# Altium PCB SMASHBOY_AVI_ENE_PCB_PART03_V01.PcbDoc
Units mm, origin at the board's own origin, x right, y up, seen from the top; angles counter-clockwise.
Board outline 215 x 83 mm, 2 copper layers (Top Layer, Bottom Layer); 21 components, 8 nets, 58 pads, 50 vias.
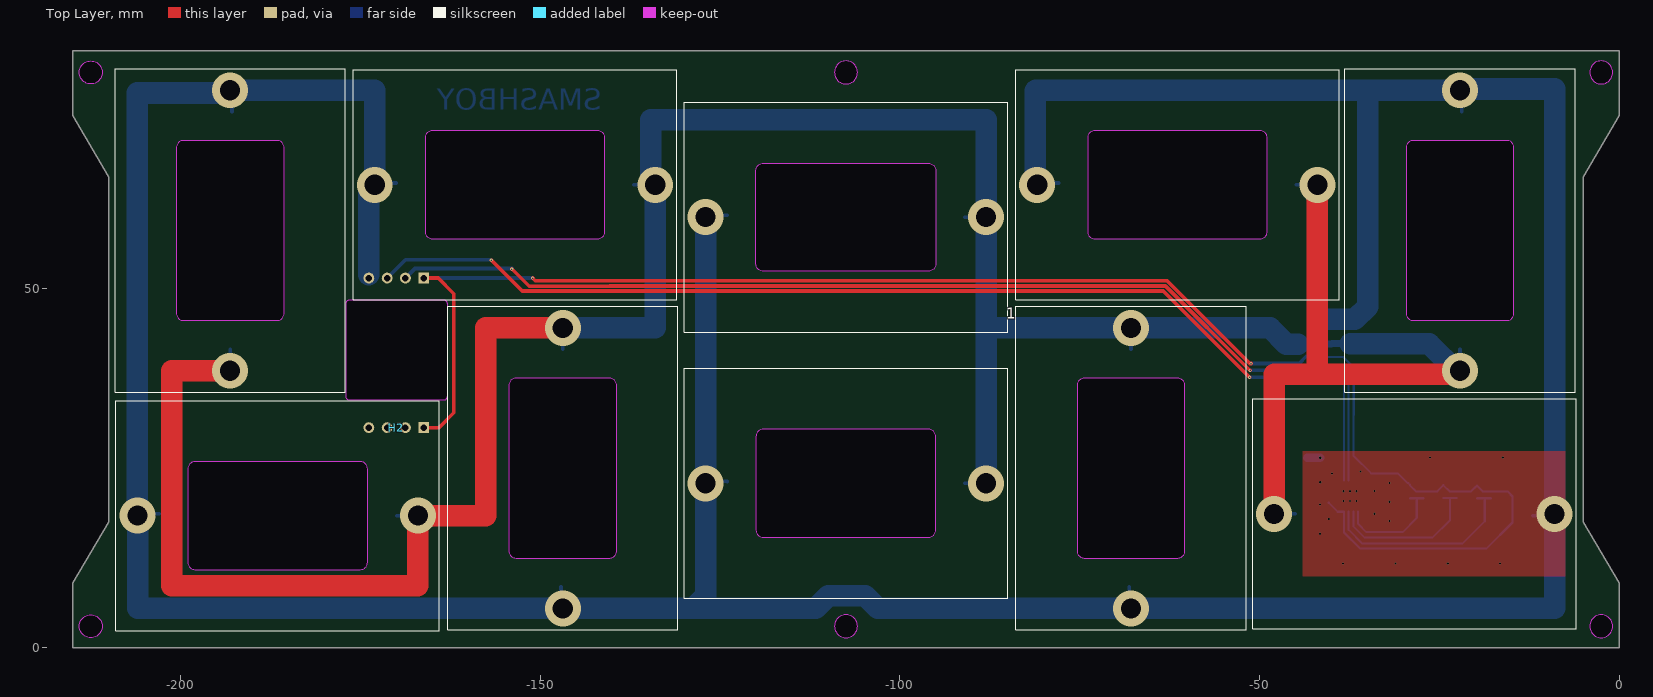
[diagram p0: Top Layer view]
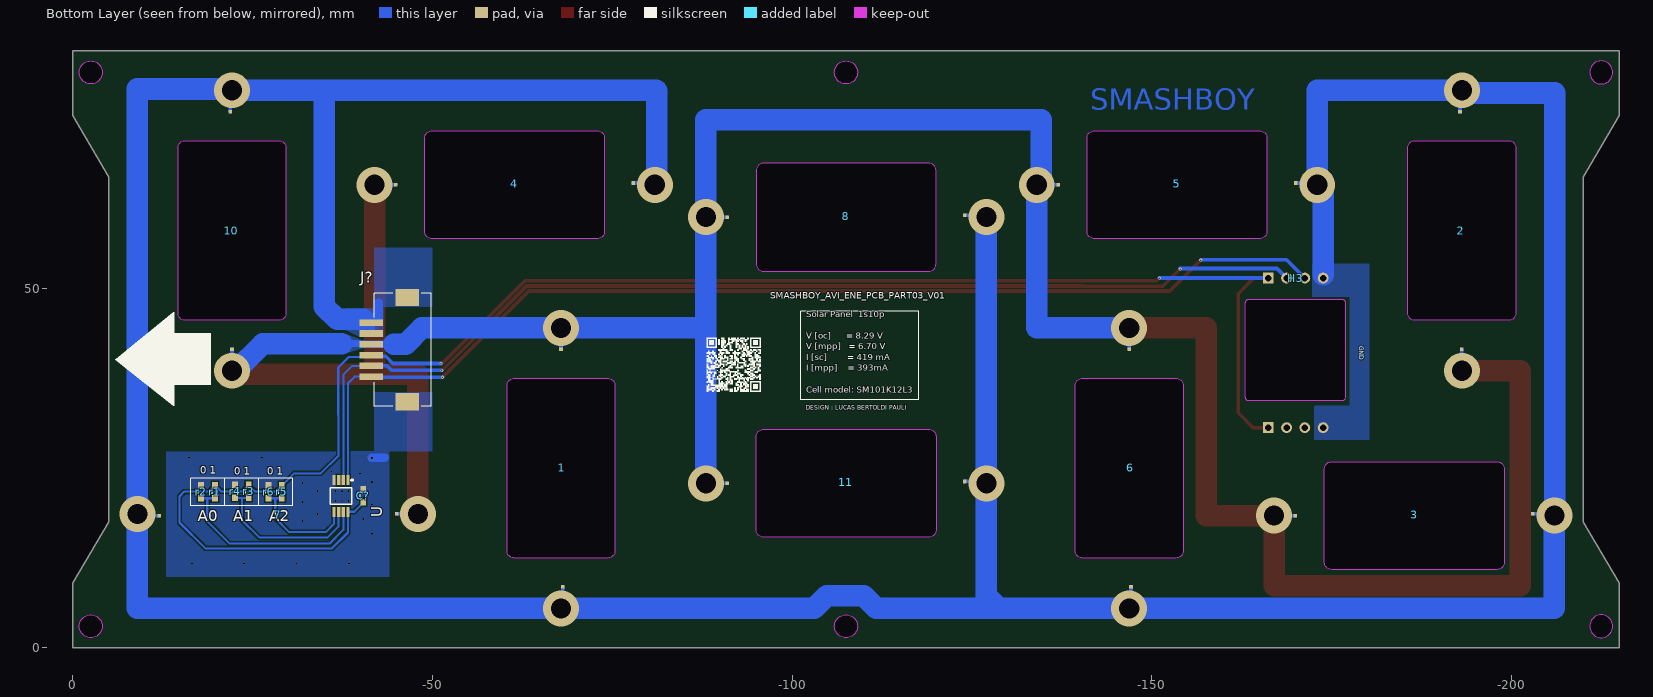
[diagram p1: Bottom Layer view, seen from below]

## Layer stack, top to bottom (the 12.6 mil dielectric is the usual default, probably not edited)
Top Solder: solder mask 0.0102, Solder Resist, Dk 3.5
Top Layer: signal copper 0.0356
Dielectric 1: dielectric 0.32, FR-4, Dk 4.8
Bottom Layer: signal copper 0.0356
Bottom Solder: solder mask 0.0102, Solder Resist, Dk 3.5

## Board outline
-215,0 -215,9.02 -210,17.52 -210,65.48 -215,73.98 -215,83 0,83 0,73.98 -5,65.48 -5,17.52 0,9.02 0,0
cut-out: -120.021,53.375 -120.021,66.375 cw(c-119.021,66.375) -119.021,67.375 -96.021,67.375 cw(c-96.021,66.375) -95.021,66.375 -95.021,53.375 cw(c-96.021,53.375) -96.021,52.375 -119.021,52.375 cw(c-119.021,53.375)
cut-out: -120.021,16.375 ccw(c-119.021,16.375) -119.021,15.375 -96.021,15.375 ccw(c-96.021,16.375) -95.021,16.375 -95.021,29.375 ccw(c-96.021,29.375) -96.021,30.375 -119.021,30.375 ccw(c-119.021,29.375) -120.021,29.375
cut-out: -176.977,34.887 -176.977,47.887 cw(c-176.477,47.887) -176.477,48.387 -163.477,48.387 cw(c-163.477,47.887) -162.977,47.887 -162.977,34.887 cw(c-163.477,34.887) -163.477,34.387 -176.477,34.387 cw(c-176.477,34.887)
cut-out: -4.1,80 ccw(c-2.5,80) -2.5,78.4 ccw(c-2.5,80) -0.9,80 ccw(c-2.5,80) -2.5,81.6 ccw(c-2.5,80)
cut-out: -4.1,3 ccw(c-2.5,3) -2.5,1.4 ccw(c-2.5,3) -0.9,3 ccw(c-2.5,3) -2.5,4.6 ccw(c-2.5,3)
cut-out: -109.1,3 ccw(c-107.5,3) -107.5,1.4 ccw(c-107.5,3) -105.9,3 ccw(c-107.5,3) -107.5,4.6 ccw(c-107.5,3)
cut-out: -109.1,80 ccw(c-107.5,80) -107.5,78.4 ccw(c-107.5,80) -105.9,80 ccw(c-107.5,80) -107.5,81.6 ccw(c-107.5,80)
cut-out: -212.5,78.4 cw(c-212.5,80) -214.1,80 cw(c-212.5,80) -212.5,81.6 cw(c-212.5,80) -210.9,80 cw(c-212.5,80)
cut-out: -212.5,1.4 cw(c-212.5,3) -214.1,3 cw(c-212.5,3) -212.5,4.6 cw(c-212.5,3) -210.9,3 cw(c-212.5,3)
cut-out: -15.625,45.521 ccw(c-15.625,46.521) -14.625,46.521 -14.625,69.521 ccw(c-15.625,69.521) -15.625,70.521 -28.625,70.521 ccw(c-28.625,69.521) -29.625,69.521 -29.625,46.521 ccw(c-28.625,46.521) -28.625,45.521
cut-out: -61.375,12.479 ccw(c-61.375,13.479) -60.375,13.479 -60.375,36.479 ccw(c-61.375,36.479) -61.375,37.479 -74.375,37.479 ccw(c-74.375,36.479) -75.375,36.479 -75.375,13.479 ccw(c-74.375,13.479) -74.375,12.479
cut-out: -73.917,57.875 ccw(c-72.917,57.875) -72.917,56.875 -49.917,56.875 ccw(c-49.917,57.875) -48.917,57.875 -48.917,70.875 ccw(c-49.917,70.875) -49.917,71.875 -72.917,71.875 ccw(c-72.917,70.875) -73.917,70.875
cut-out: -153.375,37.479 ccw(c-153.375,36.479) -154.375,36.479 -154.375,13.479 ccw(c-153.375,13.479) -153.375,12.479 -140.375,12.479 ccw(c-140.375,13.479) -139.375,13.479 -139.375,36.479 ccw(c-140.375,36.479) -140.375,37.479
cut-out: -141.021,70.875 ccw(c-142.021,70.875) -142.021,71.875 -165.021,71.875 ccw(c-165.021,70.875) -166.021,70.875 -166.021,57.875 ccw(c-165.021,57.875) -165.021,56.875 -142.021,56.875 ccw(c-142.021,57.875) -141.021,57.875
cut-out: -186.625,45.521 ccw(c-186.625,46.521) -185.625,46.521 -185.625,69.521 ccw(c-186.625,69.521) -186.625,70.521 -199.625,70.521 ccw(c-199.625,69.521) -200.625,69.521 -200.625,46.521 ccw(c-199.625,46.521) -199.625,45.521
cut-out: -199.021,11.875 ccw(c-198.021,11.875) -198.021,10.875 -175.021,10.875 ccw(c-175.021,11.875) -174.021,11.875 -174.021,24.875 ccw(c-175.021,24.875) -175.021,25.875 -198.021,25.875 ccw(c-198.021,24.875) -199.021,24.875

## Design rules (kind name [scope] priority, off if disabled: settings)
Clearance Clearance_Defferents [All] p1: gap=0.254 ignorepadtopadclearanceinfootprint=FALSE except(0.09: Arc-Arc Arc-Track Track-Track; 0.127: SMDPad-SMDPad; 0.2: Arc-SMDPad Track-SMDPad; 0.33: Arc-THPad Track-THPad; 0.5: SMDPad-THPad THPad-THPad Via-Via)
HoleSize [All] p1: absolutevalues=TRUE maxlimit=6.3 minlimit=0.025 maxpercent=80.000 minpercent=20.000
HoleToHoleClearance [All] p1: gap=0.5 allowstackedmicrovias=TRUE
PlaneConnect [All] p1: planeconnectstyle=Direct reliefexpansion=0.508 reliefentries=4 reliefconductorwidth=0.254 reliefairgap=0.254
PolygonConnect [All] p1: connectstyle=Direct reliefconductorwidth=0.254 reliefentries=4 polygonreliefangle="45 Angle" airgapwidth=0.254
RoutingTopology [All] p1: topology=Daisy_Balanced
RoutingVias [All] p1: holewidth=0.4 width=0.8 viastyle="Through Hole" minholewidth=0.3 minwidth=0.6 maxholewidth=0.5 maxwidth=1
SolderMaskExpansion [All] p1: expansion=0.102 istentingtop=FALSE
Width [All] p1: maxlimit=10 minlimit=0.09 preferedwidth=0.127
26 further rules are at their usual default settings.

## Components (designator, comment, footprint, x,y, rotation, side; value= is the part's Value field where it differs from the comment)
1 "Component_1" PCBComponent_1#1 -68,25 r270 top
2 "Component_1" PCBComponent_1#2 -193,58 r90 top
3 "Component_1" PCBComponent_1#3 -186.5,18.5 r180 top locked
4 "Component_1" PCBComponent_1#4 -61.396,64.5 r180 top
5 "Component_1" PCBComponent_1#5 -153.5,64.5 r180 top
6 "Component_1" PCBComponent_1#6 -147,25 r270 top
7 "Component_1" PCBComponent_1#7 -28.5,18.5 r0 top
8 "Component_1" PCBComponent_1#8 -107.5,60 r180 top
10 "Component_1" PCBComponent_1#9 -22,58 r90 top
11 "Component_1" PCBComponent_1#10 -107.5,23 r180 top
C? "100nF" CAP0603_060 -40.374,21.112 r270 bottom
H2 "Header 4P" Header-4P -170.03,30.611 r180 top
H3 "Header 4P" Header-4P -170.03,51.411 r180 bottom
J? "292227-6" CON6_1X6_DRH_HPI125_TYC -41.5,45.2 r270 bottom
r1 "0" RES0603 -19.761,21.685 r270 bottom
r2 "0" RES0603 -17.83,21.685 r90 bottom
r3 "0" RES0603 -24.45,21.745 r270 bottom
r4 "0" RES0603 -22.56,21.745 r90 bottom
r5 "0" RES0603 -29.06,21.7 r270 bottom
r6 "0" RES0603 -27.205,21.705 r90 bottom
U "MCP9808T-E/MS" SOP65P490X110-8N -37.285,21.105 r270 bottom

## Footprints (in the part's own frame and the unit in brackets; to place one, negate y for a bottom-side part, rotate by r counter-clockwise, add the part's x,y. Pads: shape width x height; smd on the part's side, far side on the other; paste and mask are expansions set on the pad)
CAP0603_060 [mm]
  rect 0.9x0.8 smd: 1(-0.9,0) 2(0.9,0)
  silkscreen extent -0.25,-0.4 0.25,0.4, body extent -0.8,-0.4 1.92,0.95, height 0.6
CON6_1X6_DRH_HPI125_TYC [mil]
  rect 36x130 smd: 1(0,0) 2(59.06,0) 3(118.11,0) 4(177.17,0) 5(236.22,0) 6(295.28,0)
  rect 95x130 smd: 7(-137.86,196) 8(433.14,196)
  silkscreen extent -162,16 458,329, body extent -156,-38 451,324, height 195
Header-4P [mm]
  rect 1.5x1.5 hole 0.9: 1(-3.81,0)
  round 1.5 hole 0.9: 2(-1.27,0) 3(1.27,0) 4(3.81,0)
  body extent -5.08,-1.25 5.08,1.25, height 8.52
PCBComponent_1#1 [mm]
  rect 0.5x0.5 smd far side mask+0.025: 1(-16.51,0.127) 2(16.51,-0.127)
  Bottom Layer lines w0.5: 19.431,-0.129 19.267,-0.129 19.011,-0.129 18.63,-0.128 16.51,-0.127 ; -19.479,0.125 -16.51,0.127
  silkscreen extent -22.48,-15.88 22.52,16.12, body extent -22.48,-15.88 22.52,16.13, height 1.75
PCBComponent_1#2 [mm]
  rect 0.5x0.5 smd far side mask+0.025: 1(-16.51,0.127) 2(16.51,-0.127)
  Bottom Layer lines w0.5: -16.51,0.127 -19.138,0.125 -19.479,0.125 ; 16.51,-0.127 19.138,-0.129 19.267,-0.129 19.431,-0.129
  silkscreen extent -22.48,-15.87 22.52,16.12, body extent -22.48,-15.87 22.52,16.13, height 1.75
PCBComponent_1#3 [mm]
  rect 0.5x0.5 smd far side mask+0.025: 1(-16.51,0.127) 2(16.51,-0.127)
  Bottom Layer lines w0.5: 19.431,-0.129 19.267,-0.129 18.105,-0.128 17.132,-0.127 16.51,-0.127 ; -16.51,0.127 -19.107,0.125 -19.479,0.125
  silkscreen extent -22.48,-15.88 22.52,16.12, body extent -22.48,-15.88 22.52,16.13, height 1.75
PCBComponent_1#4 [mm]
  rect 0.5x0.5 smd far side mask+0.025: 1(-16.51,0.127) 2(16.51,-0.127)
  Bottom Layer lines w0.5: 19.431,-0.129 16.51,-0.127 ; -16.51,0.127 -19.479,0.125
  silkscreen extent -22.48,-15.88 22.52,16.12, body extent -22.48,-15.88 22.52,16.13, height 1.75
PCBComponent_1#5 [mm]
  rect 0.5x0.5 smd far side: 1(-16.51,0.127) 2(16.51,-0.127)
  Bottom Layer lines w0.5: 19.431,-0.129 19.045,-0.129 16.51,-0.127 ; -16.51,0.127 -18.829,0.125 -19.478,0.125 -19.479,0.125
  silkscreen extent -22.48,-15.88 22.52,16.12, body extent -22.48,-15.88 22.52,16.13, height 1.75
PCBComponent_1#6 [mm]
  rect 0.5x0.5 smd far side mask+0.025: 1(-16.51,0.127) 2(16.51,-0.127)
  Bottom Layer lines w0.5: 19.431,-0.129 19.267,-0.129 16.51,-0.127 ; -19.479,0.125 -19.02,0.125 -16.51,0.127
  silkscreen extent -22.48,-15.88 22.52,16.12, body extent -22.48,-15.88 22.52,16.13, height 1.75
PCBComponent_1#7 [mm]
  rect 0.5x0.5 smd far side mask+0.025: 1(-16.51,0.127) 2(16.51,-0.127)
  Bottom Layer lines w0.5: -19.479,0.125 -19.172,0.125 -18.865,0.125 ; -16.51,0.127 -18.484,0.126 -18.865,0.125 ; 16.51,-0.127 17.26,-0.128 19.267,-0.129 19.431,-0.129 ; -18.865,0.125 -18.865,0.125
  silkscreen extent -22.48,-15.88 22.52,16.12, body extent -22.48,-15.88 22.52,16.12, height 1.75
PCBComponent_1#8 [mm]
  rect 0.5x0.5 smd far side mask+0.025: 1(-16.51,0.127) 2(16.51,-0.127)
  Bottom Layer lines w0.5: 19.431,-0.129 16.51,-0.127 ; -16.51,0.127 -18.264,0.126 ; -19.479,0.125 -19.035,0.125 -18.265,0.126 -18.264,0.126 ; -18.264,0.126 -18.264,0.126 ; -18.264,0.126 -18.264,0.126
  silkscreen extent -22.48,-15.88 22.52,16.12, body extent -22.48,-15.88 22.52,16.13, height 1.75
PCBComponent_1#9 [mm]
  rect 0.5x0.5 smd far side mask+0.025: 1(-16.51,0.127) 2(16.51,-0.127)
  Bottom Layer lines w0.5: -16.51,0.127 -19,0.125 -19,0.125 -19.479,0.125 ; 16.51,-0.127 18.215,-0.128 19.165,-0.129 19.29,-0.129 19.418,-0.129 19.431,-0.129
  silkscreen extent -22.48,-15.88 22.52,16.12, body extent -22.48,-15.88 22.52,16.13, height 1.75
PCBComponent_1#10 [mm]
  rect 0.5x0.5 smd far side mask+0.025: 1(-16.51,0.127) 2(16.51,-0.127)
  Bottom Layer lines w0.5: 19.431,-0.129 16.51,-0.127 ; -16.51,0.127 -18.266,0.126 -19.24,0.125 -19.479,0.125
  silkscreen extent -22.48,-15.88 22.52,16.12, body extent -22.48,-15.88 22.52,16.13, height 1.75
RES0603 [mm]
  rect 0.9x0.8 smd: 1(-0.9,0) 2(0.9,0)
  silkscreen extent -0.25,-0.4 0.25,0.4, body extent -1.05,-0.4 1.92,0.95, height 0.5
SOP65P490X110-8N [mm]
  rect 1.4x0.45 smd: 1(-2.2,0.975) 2(-2.2,0.325) 3(-2.2,-0.325) 4(-2.2,-0.975) 5(2.2,-0.975) 6(2.2,-0.325) 7(2.2,0.325) 8(2.2,0.975)
  silkscreen extent -2.39,-1.5 1.17,1.73, body extent -2.32,-1.5 2.58,1.5, height 1.15

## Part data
C?: library part CAP0603, "Capacitor SDM 0603"
H2 H3: library part Header-4P, "Header 4 Pinos"
J?: "No Description Available"
r1 r2 r3 r4 r5 r6: library part RES0603, "Resistor SMD 0603"
U: "Temperature Sensor Digital, Local -40Â°C ~ 125Â°C 10 b 8-MSOP", Package="MSOP-8 Microchip"

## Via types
v1: diameter 0.3, hole 0.3, Top Layer to Bottom Layer, 24 vias
v2: diameter 5, hole 2.8, Top Layer to Bottom Layer, 20 vias
v3: diameter 0.45, hole 0.2, Top Layer to Bottom Layer, 6 vias

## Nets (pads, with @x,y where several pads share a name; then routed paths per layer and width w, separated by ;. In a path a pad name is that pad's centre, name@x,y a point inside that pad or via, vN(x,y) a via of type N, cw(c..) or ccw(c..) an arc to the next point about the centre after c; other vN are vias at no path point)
GND: 1.2 2.2 3.2 4.2 5.2 6.2 7.2 8.2 10.2 11.2 C?.1 H2.4 H3.4 J?.1 J?.2 r2.2 r4.2 r6.2 U.4 | length 585.7
  Top Layer w3: v2@-173.84,64.688 v2@-173.84,64.375 ; v2@-173.404,63.938 v2@-173.84,64.375 ; v2(-173.021,64.375) v2@-173.84,64.375
  Bottom Layer w1: J?.2 J?.1
  Bottom Layer w1.2: -43.389,26.428 v1(-41.552,26.428) ; -42.504,47.947 -42.504,45.946 -42.066,45.946
  Bottom Layer w3: H3.4@-173.84,51.863 v2@-173.84,64.375 ; v2(-173.021,64.375) -172.95,64.375 -173.021,64.446 -173.021,77.521 v2(-193.125,77.521) -193.508,77.138 -206.021,77.138 v2(-206.021,18.375) -205.975,18.329 -205.975,5.479 v2(-146.875,5.479) -128.778,5.479 ; v2@-127.025,60.035 -127.025,22.879 v2(-127.021,22.875) -127.021,7.236 -128.778,5.479 ; -81.185,77.48 -81.185,64.539 v2@-81.021,64.375 ; -81.145,77.521 -34.98,77.521 ; -40.374,45.657 -36.737,45.657 -34.98,47.415 -34.98,77.521 ; v2@-21.872,77.7 -8.979,77.7 -8.979,46.295 v2(-8.979,18.625) -8.979,5.479 v2(-67.875,5.479) -99.16,5.479 -103.079,5.479 -104.836,7.236 -109.969,7.236 -111.726,5.479 -128.778,5.479 ; v2@-21.871,77.29 -22.102,77.521 v2(-22.125,77.521) -34.98,77.521
  other v1: -38.375,11.715 -31.103,11.715 -23.831,11.715 -16.559,11.715 -41.59,15.853 -31.91,17.624 -40.374,17.886 -34,18.627 -41.59,19.915 -31.91,20.315 -38.31,20.42 -37.435,20.42 -36.535,20.42 -38.31,21.77 -37.435,21.77 -36.535,21.77 -34,21.785 -31.91,22.9 -41.552,23.008 -39.936,24.228 -35.95,24.51 -26.29,26.455 -16.19,26.455
  other v2: -127.021,59.875 -80.917,64.375
Net1_1: 1.1 2.1 3.1 4.1 5.1 6.1 7.1 8.1 10.1 11.1 J?.3 | length 406.5
  Top Layer w0.5: v2@-42.021,64.375 -41.995,64.375 v2@-41.995,63.97
  Top Layer w3: v2@-193.069,38.521 v2(-193.125,38.521) -201.256,38.521 -201.256,8.646 -167.021,8.646 v2(-167.021,18.375) -157.593,18.375 -157.593,44.479 v2(-146.875,44.479) ; v2(-47.979,18.625) -47.979,38.015 -41.995,38.015 ; v2@-41.995,63.97 -41.995,38.015 ; v2@-22.125,38.015 -41.995,38.015
  Bottom Layer w0.5: v2@-48.129,18.877 -48.129,18.625 v2(-47.979,18.625)
  Bottom Layer w1: -44.651,42.2 J?.3 -41.457,42.243 -39.996,42.243 -39.943,42.295 -37.395,42.295
  Bottom Layer w3: v2(-146.875,44.479) -134.021,44.479 v2(-134.021,64.375) ; v2@-134.671,64.375 -134.671,73.415 -88.021,73.415 v2(-88.021,59.875) ; v2(-88.021,22.875) -88.021,44.479 ; v2@-88.021,58.659 -88.021,44.479 ; -44.651,42.2 -46.265,42.2 -48.544,44.479 v2(-67.875,44.479) -88.021,44.479 ; -37.395,42.295 -26.44,42.295 -22.666,38.521 v2(-22.125,38.521)
  other v2: -41.917,64.375
NetC?_2: C?.2 H2.1 H3.1 J?.4 r1.1 r3.1 r5.1 U.8 | length 235.5
  Top Layer w0.5: H3.1 -164.193,51.411 -162.02,49.238 -162.02,32.668 -164.078,30.611 H2.1 ; v3(-151.072,51.411) -150.694,51.032 -62.87,51.032 -51.356,39.519 -51.351,39.524 v3(-51.191,39.524)
  Bottom Layer w0.3: J?.4 -41.231,40.431 -38.361,40.431 -36.9,38.969 -36.9,32.366 -36.935,32.366 -36.935,26.7 -34.49,24.255 -30.765,24.255 -29.41,22.9 -29.31,22.9 -29.06,22.65 r5.1 -29.06,22.55 -28.255,21.745 -25.3,21.745 r3.1@-24.45,22.595 ; C?.2 -40.374,20.162 -39.117,18.905 U.8 -38.26,16.04 -36.04,13.82 -18.425,13.82 -14.825,17.42 -14.825,21.045 -15.5,21.72 -18.946,21.72 -19.511,22.285 r1.1@-19.761,22.535 ; r3.1 r3.1@-24.45,22.595 ; r1.1 r1.1@-19.761,22.535 ; r3.1@-24.45,22.595 -23.6,21.745 -20.601,21.745 -20.061,22.285 -20.011,22.285 r1.1@-19.761,22.535
  Bottom Layer w0.5: H3.1 v3(-151.072,51.411) ; v3(-51.191,39.524) -44.493,39.524 -44.488,39.519 -43.488,40.519 -41.681,40.519 J?.4
NetH3_2: H3.2 J?.5 U.2 | length 153.1
  Top Layer w0.3: -140.392,50.268 -140.355,50.306
  Top Layer w0.5: v3@-153.984,52.679 v3(-153.965,52.66) -153.947,52.642 -153.909,52.642 -151.536,50.268 -140.392,50.268 ; -140.355,50.306 -63.087,50.306 -51.352,38.571 v3(-51.318,38.571)
  Bottom Layer w0.3: v3(-51.318,38.571) v3@-51.308,38.581 ; J?.5@-41.781,39.207 -41.774,39.2 J?.5 -38.829,39.2 -37.61,37.981 U.2
  Bottom Layer w0.5: H3.2 -167.43,52.741 v3@-153.928,52.741 ; v3@-51.308,38.581 -44.317,38.581 -43.691,39.207 J?.5@-41.781,39.207
NetH3_3: H3.3 J?.6 U.1 | length 155.1
  Top Layer w0.5: v3(-156.82,53.91) -152.517,49.608 -63.386,49.608 v3(-51.391,37.613)
  Bottom Layer w0.3: J?.6@-41.997,37.613 -41.844,37.767 -41.562,37.485 -41.5,37.547 J?.6 -39.176,37.7 -38.26,36.784 U.1
  Bottom Layer w0.5: H3.3 -168.738,53.974 v3@-156.82,53.974 ; v3(-51.391,37.613) J?.6@-41.997,37.613
Netr1_2: r1.2 r2.1 U.7 | length 28.6
  Bottom Layer w0.3: U.7 -37.61,16.41 -35.685,14.485 -21.815,14.485 -18.695,17.605 -18.695,20.697 -18.607,20.785 ; r1.2 -18.607,20.785 ; r2.1 -18.607,20.785
Netr3_2: r3.2 r4.1 U.6 | length 22.1
  Bottom Layer w0.3: U.6@-36.985,18.88 U.6 -36.96,16.885 -35.395,15.32 -25.965,15.32 -23.505,17.78 -23.505,20.845 ; r3.2 -23.505,20.845 ; r4.1 -23.505,20.845
Netr5_2: r5.2 r6.1 U.5 | length 15.8
  Bottom Layer w0.3: U.5 -36.31,17.235 -35.155,16.08 -30.095,16.08 -28.132,18.043 -28.132,20.8 ; r5.2 -28.132,20.8 ; r6.1 -27.205,20.8 -28.132,20.8
pads on no net: H2.2 H2.3 J?.7 J?.8 U.3

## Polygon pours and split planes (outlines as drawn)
GND on Top Solder "NONET_L-01_P-001" (solid): -42.159,26.013 -14.799,26.013 -14.799,11.237 -42.079,11.237 -42.079,11.392
GND on Top Solder "NONET_L02_P003" (solid, pour order 3): -39.2,22.365 -39.2,19.88 -35.445,19.88 -35.445,22.38
GND on Top Layer "GND_L01_P001" (solid, pour order 1): -43.985,27.297 -7.49,27.297 -7.49,9.952 -44.025,9.952
GND on Bottom Solder "NONET_L-01_P-001" (solid): -35.225,22.325 -35.225,19.885 -39.24,19.885 -39.24,22.341
GND on Bottom Layer "NONET_L-01_P-001" (solid, pour order 20): -172.349,53.457 -172.349,48.824 -177.552,48.824 -177.552,33.671 -172.591,33.671 -172.591,28.941 -180.248,28.941 -180.248,53.43
GND on Bottom Layer "NONET_L-01_P-001" (solid, pour order 19): -41.875,30.236 -41.875,27.086 -43.979,27.086 -43.979,30.242
GND on Bottom Layer "NONET_L-01_P-001" (solid, pour order 18): -49.947,47.396 -49.947,55.65 -41.874,55.65 -41.874,47.437 -41.965,47.437
GND on Bottom Layer "NONET_L-01_P-001" (solid, pour order 15): -41.875,35.583 -41.875,27.348 -49.948,27.348 -49.948,35.542 -49.857,35.542
Net1_1 on Bottom Layer "NONET_L-01_P-001" (solid, pour order 9): -37.994,43.602 -40.505,42.672 -40.505,41.74 -37.935,40.895
GND on Bottom Layer "NONET_L-01_P-001" (solid, pour order 8): -38.1,47.195 -43.151,47.195 -43.151,43.243 -39.849,43.243 -38.035,44.157
GND on Bottom Layer "NONET_L-01_P-001" (solid, pour order 7): -43.979,27.368 -43.979,9.882 -12.979,9.882 -12.979,27.253

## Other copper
Bottom Layer:
  text "SMASHBOY" at -141.46,73.845 h5

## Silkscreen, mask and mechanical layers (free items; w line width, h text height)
Bottom Overlay:
  drawing of 46 lines, arcs and shapes, not listed
  text "SMASHBOY_AVI_ENE_PCB_PART03_V01" at -96.962,48.183 h1.52
  text "GND" at -178.666,41.934 h1 r90
  text "Solar Panel  1s10p /  / V [oc]      = 8.29 V / V [mpp]   = 6.70 V / I [sc]        = 419 mA / I [mpp]    = 393mA /  / Cell model: SM101K12L3" at -101.952,35.143 h1.5
  text "DESIGN : LUCAS BERTOLDI PAULI" at -101.927,32.859 h1
  text "0 1" at -17.709,24.178 h1
  text "0 1" at -27.029,24.068 h1
  text "0 1" at -22.449,24.043 h1
  text "A0" at -17.359,17.603 h1.52
  text "A2" at -27.304,17.583 h1.52
  text "A1" at -22.284,17.583 h1.52
Mechanical 1:
  circle w0.1: c-2.5,80 r1.6
  circle w0.1: c-2.5,3 r1.6
  circle w0.1: c-107.5,3 r1.6
  circle w0.1: c-107.5,80 r1.6
  circle w0.1: c-212.5,80 r1.6
  circle w0.1: c-212.5,3 r1.6
  lines w0.1: -215,0 0,0 0,9.02 -5,17.52 -5,65.48 0,73.98 0,83 -215,83 -215,73.98 -210,65.48 -210,17.52 -215,9.02 -215,0 ; -200.625,46.521 ccw(c-199.625,46.521) -199.625,45.521 -186.625,45.521 ccw(c-186.625,46.521) -185.625,46.521 -185.625,69.521 ccw(c-186.625,69.521) -186.625,70.521 -199.625,70.521 ccw(c-199.625,69.521) -200.625,69.521 -200.625,46.521 ; -199.021,11.875 ccw(c-198.021,11.875) -198.021,10.875 -175.021,10.875 ccw(c-175.021,11.875) -174.021,11.875 -174.021,24.875 ccw(c-175.021,24.875) -175.021,25.875 -198.021,25.875 ccw(c-198.021,24.875) -199.021,24.875 -199.021,11.875 ; -176.977,34.887 ccw(c-176.477,34.887) -176.477,34.387 -163.477,34.387 ccw(c-163.477,34.887) -162.977,34.887 -162.977,47.887 ccw(c-163.477,47.887) -163.477,48.387 -176.477,48.387 ccw(c-176.477,47.887) -176.977,47.887 -176.977,34.887 ; -166.021,57.875 ccw(c-165.021,57.875) -165.021,56.875 -142.021,56.875 ccw(c-142.021,57.875) -141.021,57.875 -141.021,70.875 ccw(c-142.021,70.875) -142.021,71.875 -165.021,71.875 ccw(c-165.021,70.875) -166.021,70.875 -166.021,57.875 ; -154.375,13.479 ccw(c-153.375,13.479) -153.375,12.479 -140.375,12.479 ccw(c-140.375,13.479) -139.375,13.479 -139.375,36.479 ccw(c-140.375,36.479) -140.375,37.479 -153.375,37.479 ccw(c-153.375,36.479) -154.375,36.479 -154.375,13.479 ; -120.03,16.385 ccw(c-119.03,16.385) -119.03,15.385 -96.03,15.385 ccw(c-96.03,16.385) -95.03,16.385 -95.03,29.385 ccw(c-96.03,29.385) -96.03,30.385 -119.03,30.385 ccw(c-119.03,29.385) -120.03,29.385 -120.03,16.385 ; -120.03,53.385 ccw(c-119.03,53.385) -119.03,52.385 -96.03,52.385 ccw(c-96.03,53.385) -95.03,53.385 -95.03,66.385 ccw(c-96.03,66.385) -96.03,67.385 -119.03,67.385 ccw(c-119.03,66.385) -120.03,66.385 -120.03,53.385 ; -75.375,13.479 ccw(c-74.375,13.479) -74.375,12.479 -61.375,12.479 ccw(c-61.375,13.479) -60.375,13.479 -60.375,36.479 ccw(c-61.375,36.479) -61.375,37.479 -74.375,37.479 ccw(c-74.375,36.479) -75.375,36.479 -75.375,13.479 ; -73.917,57.875 ccw(c-72.917,57.875) -72.917,56.875 -49.917,56.875 ccw(c-49.917,57.875) -48.917,57.875 -48.917,70.875 ccw(c-49.917,70.875) -49.917,71.875 -72.917,71.875 ccw(c-72.917,70.875) -73.917,70.875 -73.917,57.875 ; -29.625,46.521 ccw(c-28.625,46.521) -28.625,45.521 -15.625,45.521 ccw(c-15.625,46.521) -14.625,46.521 -14.625,69.521 ccw(c-15.625,69.521) -15.625,70.521 -28.625,70.521 ccw(c-28.625,69.521) -29.625,69.521 -29.625,46.521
